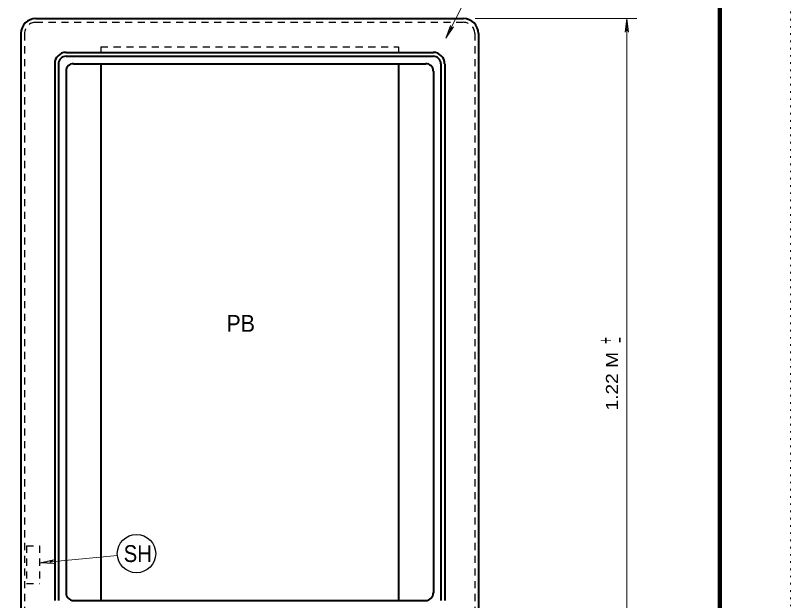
# Model space of a CAD drawing. Extents: x 312583 to 312854, y 144419 to 144597.
# Drawn here: x 312804.21 to 312853.5, y 144529.81 to 144567.02 of the extents above; entities that cross this region are included whole.
import ezdxf
from ezdxf.enums import TextEntityAlignment as Align

# ---------------------------------------------------------------- set-up
doc = ezdxf.new("R2010")
doc.units = 0
doc.header["$LTSCALE"] = 0.3
doc.linetypes.add('DOTTED', pattern=[1.5, 0.3, -1.2])
doc.linetypes.add('SHORT_DASHED', pattern=[2.7, 1.5, -1.2])
doc.layers.add('1', color=7, linetype='Continuous', lineweight=25)
doc.layers.add('2', color=7, linetype='Continuous', lineweight=13)

msp = doc.modelspace()

# ---------------------------------------------------------------- linework, layer by layer
at = {"layer": '1', "lineweight": 158}
msp.add_line((312849, 144423.1446), (312849, 144585.0846), dxfattribs=at)
at = {"layer": '1', "lineweight": 40}
for p, q in [((312805.507, 144566.8256), (312832.7007, 144566.8256)), ((312804.5487, 144565.8673), (312804.5487, 144527.2963)), ((312833.659, 144565.8673), (312833.659, 144527.2963)), ((312807.4237, 144564.6713), (312830.784, 144564.6713)), ((312807.4237, 144564.4336), (312830.784, 144564.4336)), ((312806.703, 144563.9506), (312806.703, 144529.811)), ((312806.9407, 144563.9506), (312806.9407, 144529.811)), ((312807.899, 144563.9506), (312830.301, 144563.9506)), ((312809.6393, 144563.9506), (312809.6393, 144529.811)), ((312828.5683, 144563.9506), (312828.5683, 144529.811)), ((312831.2593, 144563.9506), (312831.2593, 144529.811)), ((312831.5047, 144563.9506), (312831.5047, 144529.811)), ((312807.4237, 144563.4753), (312807.4237, 144530.2863)), ((312830.784, 144563.4753), (312830.784, 144530.2863)), ((312807.899, 144529.811), (312830.301, 144529.811))]:
    msp.add_line(p, q, dxfattribs=at)
at = {"layer": '1', "linetype": 'SHORT_DASHED'}
for p, q in [((312805.507, 144566.588), (312832.7007, 144566.588)), ((312804.7863, 144565.8673), (312804.7863, 144527.2963)), ((312833.4213, 144565.8673), (312833.4213, 144527.2963)), ((312809.6393, 144565.0316), (312828.5683, 144565.0316)), ((312809.6393, 144565.0316), (312809.6393, 144564.6713)), ((312828.5683, 144565.0316), (312828.5683, 144564.6713)), ((312804.909, 144533.284), (312805.7447, 144533.284)), ((312804.909, 144533.284), (312804.909, 144530.892)), ((312805.7447, 144533.284), (312805.7447, 144530.892)), ((312804.909, 144530.892), (312805.7447, 144530.892))]:
    msp.add_line(p, q, dxfattribs=at)
at = {"layer": '1', "linetype": 'DOTTED', "lineweight": 13}
msp.add_lwpolyline([(312601.2, 144418.5846), (312853.5, 144418.5846), (312853.5, 144596.7846)], dxfattribs=at)
at = {"layer": '1', "lineweight": 40}
for centre, radius, start, end in [((312805.5051, 144565.8673), 0.9583, 90, 180), ((312832.6987, 144565.8673), 0.9583, 0, 90), ((312807.4217, 144563.9506), 0.7188, 90, 180), ((312807.4217, 144563.9506), 0.4792, 90, 180), ((312830.7821, 144563.9506), 0.7188, 0, 90), ((312830.7821, 144563.9506), 0.4792, 0, 90), ((312807.9009, 144563.4715), 0.4792, 90, 180), ((312830.3029, 144563.4715), 0.4792, 0, 90), ((312807.9009, 144530.2892), 0.4792, 180, 270), ((312830.3029, 144530.2892), 0.4792, 270, 0)]:
    msp.add_arc(centre, radius, start, end, dxfattribs=at)
at = {"layer": '1', "linetype": 'SHORT_DASHED'}
for centre, start, end in [((312805.5051, 144565.8673), 90, 180), ((312832.6987, 144565.8673), 0, 90)]:
    msp.add_arc(centre, 0.7188, start, end, dxfattribs=at)
at = {"layer": '2'}
for p, q in [((312833.1683, 144568.6963), (312831.5737, 144565.5683)), ((312833.4443, 144566.8256), (312843.7253, 144566.8256)), ((312843.0813, 144566.8256), (312842.974, 144565.9593)), ((312843.0813, 144520.8256), (312843.0813, 144566.8256)), ((312843.0813, 144566.8256), (312843.1887, 144565.9593)), ((312831.5737, 144565.5683), (312831.8727, 144566.3886)), ((312831.5737, 144565.5683), (312832.0643, 144566.2966)), ((312831.8727, 144566.3886), (312831.842, 144566.0973)), ((312832.0643, 144566.2966), (312831.842, 144566.0973)), ((312842.974, 144565.9593), (312843.0813, 144566.2353)), ((312843.1887, 144565.9593), (312843.0813, 144566.2353)), ((312805.783, 144532.1953), (312810.6897, 144532.6783)), ((312805.783, 144532.1953), (312806.634, 144532.387)), ((312805.783, 144532.1953), (312806.657, 144532.1723)), ((312806.634, 144532.387), (312806.3733, 144532.2566)), ((312806.657, 144532.1723), (312806.3733, 144532.2566))]:
    msp.add_line(p, q, dxfattribs=at)
at = {"layer": '2', "lineweight": 25}
msp.add_circle((312811.9039, 144532.7933), 1.2209, dxfattribs=at)

# ---------------------------------------------------------------- texts
at = {"layer": '2'}
for s, width, p in [('PB', 0.95, (312818.5326, 144546.9)), ('SH', 0.9, (312811.9853, 144532.2566))]:
    msp.add_text(s, height=1.072, dxfattribs=dict(at, width=width)).set_placement(p, align=Align.CENTER)
at = {"layer": '2', "width": 0.6}
msp.add_text('+', height=0.92, rotation=90, dxfattribs=at).set_placement((312842.1997, 144546.3556), align=Align.CENTER)
at = {"layer": '2'}
msp.add_text('-', height=0.92, rotation=90, dxfattribs=at).set_placement((312842.997, 144546.371), align=Align.CENTER)
at = {"layer": '2', "width": 1.2}
msp.add_text('1.22 M', height=0.76, rotation=90, dxfattribs=at).set_placement((312842.5236, 144541.8913))

doc.saveas('drawing.dxf')
